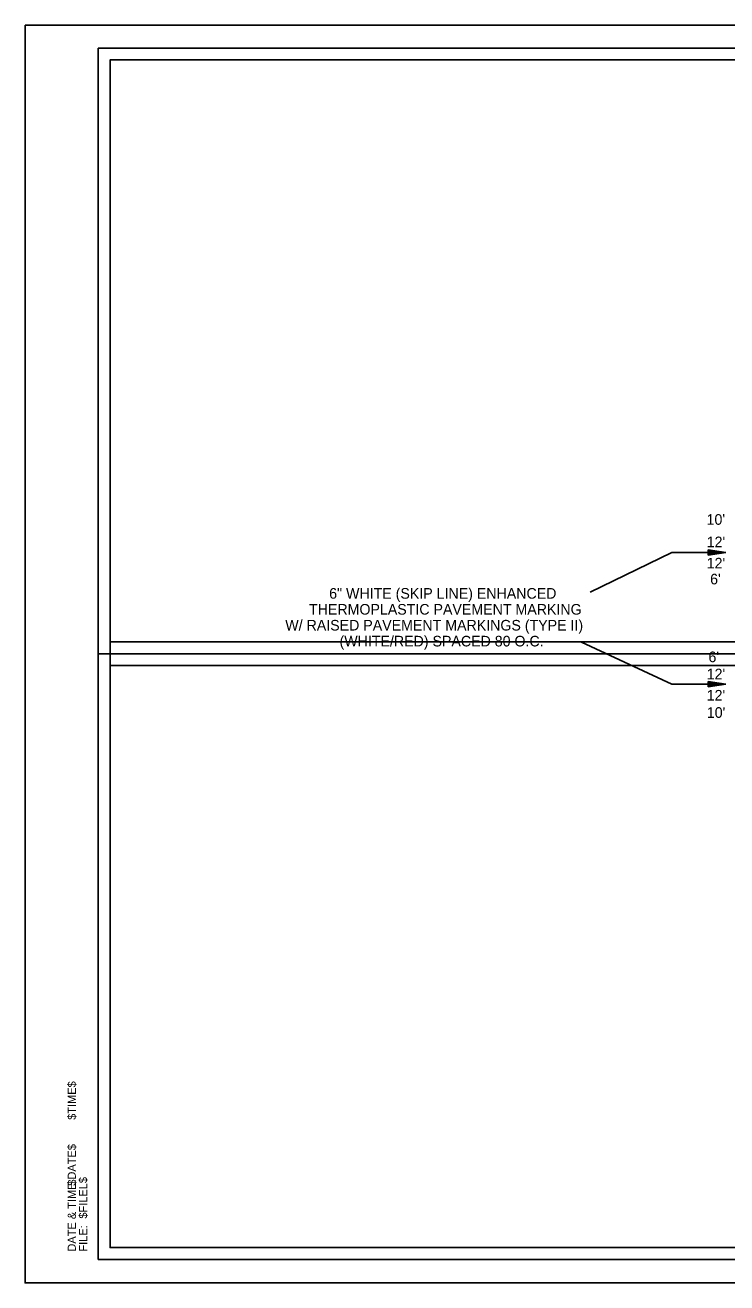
# Model space of a CAD drawing. Extents: x 1369905 to 1370238, y 380119 to 380332.
# Drawn here: x 1369904.7 to 1370023.8, y 380119.1 to 380332.4 of the extents above; entities that cross this region are included whole.
import ezdxf

# ---------------------------------------------------------------- set-up
doc = ezdxf.new("R2010")
doc.units = 0
for name, color, linetype in [('Default', 7, 'Continuous'), ('R_Border', 7, 'Continuous'), ('R_Border Notes', 7, 'Continuous'), ('R_Border Plan-Plan', 7, 'Continuous'), ('R_No Plot', 7, 'Continuous'), ('R_Proposed Road', 7, 'Continuous')]:
    doc.layers.add(name, color=color, linetype=linetype)

msp = doc.modelspace()

# ---------------------------------------------------------------- linework, layer by layer
at = {"layer": 'Default'}
for p, q in [((1370020.65, 380243.42), (1370023.65, 380242.97)), ((1370020.65, 380243.42), (1370020.65, 380242.52)), ((1370020.65, 380243.42), (1370023.65, 380242.97)), ((1370020.65, 380243.42), (1370020.65, 380242.52)), ((1370020.65, 380243.42), (1370023.65, 380242.97)), ((1370020.65, 380243.42), (1370020.65, 380242.52)), ((1370020.65, 380243.33), (1370023.15, 380242.97)), ((1370020.65, 380243.33), (1370023.15, 380242.97)), ((1370020.65, 380243.33), (1370023.15, 380242.97)), ((1370020.65, 380243.27), (1370022.63, 380242.97)), ((1370020.65, 380243.27), (1370022.63, 380242.97)), ((1370020.65, 380243.27), (1370022.63, 380242.97)), ((1370020.65, 380243.18), (1370022.13, 380242.97)), ((1370020.65, 380243.18), (1370022.13, 380242.97)), ((1370020.65, 380243.18), (1370022.13, 380242.97)), ((1370020.65, 380243.12), (1370021.62, 380242.97)), ((1370020.65, 380243.12), (1370021.62, 380242.97)), ((1370020.65, 380243.12), (1370021.62, 380242.97)), ((1370020.65, 380243.03), (1370021.12, 380242.97)), ((1370020.65, 380243.03), (1370021.12, 380242.97)), ((1370020.65, 380243.03), (1370021.12, 380242.97)), ((1370020.65, 380242.52), (1370023.65, 380242.97)), ((1370020.65, 380242.82), (1370021.62, 380242.97)), ((1370020.65, 380242.67), (1370022.63, 380242.97)), ((1370020.65, 380242.6), (1370023.15, 380242.97)), ((1370020.65, 380242.75), (1370022.13, 380242.97)), ((1370020.65, 380242.9), (1370021.12, 380242.97)), ((1370020.65, 380242.52), (1370023.65, 380242.97)), ((1370020.65, 380242.82), (1370021.62, 380242.97)), ((1370020.65, 380242.67), (1370022.63, 380242.97)), ((1370020.65, 380242.6), (1370023.15, 380242.97)), ((1370020.65, 380242.75), (1370022.13, 380242.97)), ((1370020.65, 380242.9), (1370021.12, 380242.97)), ((1370020.65, 380242.52), (1370023.65, 380242.97)), ((1370020.65, 380242.82), (1370021.62, 380242.97)), ((1370020.65, 380242.67), (1370022.63, 380242.97)), ((1370020.65, 380242.6), (1370023.15, 380242.97)), ((1370020.65, 380242.75), (1370022.13, 380242.97)), ((1370020.65, 380242.9), (1370021.12, 380242.97)), ((1370020.65, 380221.06), (1370023.65, 380220.61)), ((1370020.65, 380220.16), (1370020.65, 380221.06)), ((1370020.65, 380221.06), (1370023.65, 380220.61)), ((1370020.65, 380220.16), (1370020.65, 380221.06)), ((1370020.65, 380221.06), (1370023.65, 380220.61)), ((1370020.65, 380220.16), (1370020.65, 380221.06)), ((1370020.65, 380220.98), (1370023.15, 380220.61)), ((1370020.65, 380220.98), (1370023.15, 380220.61)), ((1370020.65, 380220.98), (1370023.15, 380220.61)), ((1370020.65, 380220.91), (1370022.63, 380220.61)), ((1370020.65, 380220.91), (1370022.63, 380220.61)), ((1370020.65, 380220.91), (1370022.63, 380220.61)), ((1370020.65, 380220.83), (1370022.13, 380220.61)), ((1370020.65, 380220.83), (1370022.13, 380220.61)), ((1370020.65, 380220.83), (1370022.13, 380220.61)), ((1370020.65, 380220.76), (1370021.62, 380220.61)), ((1370020.65, 380220.76), (1370021.62, 380220.61)), ((1370020.65, 380220.76), (1370021.62, 380220.61)), ((1370020.65, 380220.68), (1370021.12, 380220.61)), ((1370020.65, 380220.68), (1370021.12, 380220.61)), ((1370020.65, 380220.68), (1370021.12, 380220.61)), ((1370020.65, 380220.16), (1370023.65, 380220.61)), ((1370020.65, 380220.46), (1370021.62, 380220.61)), ((1370020.65, 380220.31), (1370022.63, 380220.61)), ((1370020.65, 380220.24), (1370023.15, 380220.61)), ((1370020.65, 380220.39), (1370022.13, 380220.61)), ((1370020.65, 380220.54), (1370021.12, 380220.61)), ((1370020.65, 380220.16), (1370023.65, 380220.61)), ((1370020.65, 380220.46), (1370021.62, 380220.61)), ((1370020.65, 380220.31), (1370022.63, 380220.61)), ((1370020.65, 380220.24), (1370023.15, 380220.61)), ((1370020.65, 380220.39), (1370022.13, 380220.61)), ((1370020.65, 380220.54), (1370021.12, 380220.61)), ((1370020.65, 380220.16), (1370023.65, 380220.61)), ((1370020.65, 380220.46), (1370021.62, 380220.61)), ((1370020.65, 380220.31), (1370022.63, 380220.61)), ((1370020.65, 380220.24), (1370023.15, 380220.61)), ((1370020.65, 380220.39), (1370022.13, 380220.61)), ((1370020.65, 380220.54), (1370021.12, 380220.61))]:
    msp.add_line(p, q, dxfattribs=at)
at = {"layer": 'R_Border'}
for p, q in [((1369917.1, 380328.52), (1370233.28, 380328.52)), ((1369917.1, 380123.06), (1369917.1, 380328.52)), ((1369917.1, 380123.06), (1369917.1, 380123.06)), ((1370233.28, 380123.06), (1369917.1, 380123.06))]:
    msp.add_line(p, q, dxfattribs=at)
at = {"layer": 'R_Border Plan-Plan'}
msp.add_line((1369917.1, 380225.79), (1370233.28, 380225.79), dxfattribs=at)
at = {"layer": 'R_No Plot'}
for points in [[(1369904.69, 380332.42), (1370238.03, 380332.42), (1370238.03, 380119.08), (1369904.69, 380119.08)], [(1370231.28, 380227.79), (1369919.1, 380227.79), (1369919.1, 380326.52), (1370168.64, 380326.52), (1370168.64, 380316.64), (1370186.18, 380316.64), (1370210.28, 380316.64), (1370210.28, 380294.31), (1370231.28, 380294.31)], [(1369919.1, 380326.52), (1370168.64, 380326.52), (1370168.64, 380316.64), (1370186.18, 380316.64), (1370210.28, 380316.64), (1370210.28, 380294.31), (1370231.28, 380294.31), (1370231.28, 380125.06), (1369919.1, 380125.06)], [(1369919.1, 380223.79), (1370231.28, 380223.79), (1370231.28, 380125.06), (1369919.1, 380125.06)]]:
    msp.add_lwpolyline(points, close=True, dxfattribs=at)
at = {"layer": 'R_Proposed Road'}
for p, q in [((1370014.44, 380242.97), (1370023.65, 380242.97)), ((1370014.44, 380242.97), (1370023.65, 380242.97)), ((1370014.44, 380220.61), (1370023.65, 380220.61)), ((1370014.44, 380220.61), (1370023.65, 380220.61))]:
    msp.add_line(p, q, dxfattribs=at)
for points in [[(1370000.62, 380236.26), (1370014.44, 380242.97), (1370023.65, 380242.97)], [(1369999.13, 380227.74), (1370014.44, 380220.61), (1370023.65, 380220.61)]]:
    msp.add_lwpolyline(points, dxfattribs=at)

# ---------------------------------------------------------------- texts
at = {"layer": 'Default'}
for s, p in [("10'", (1370020.36, 380247.67)), ("12'", (1370020.38, 380243.86)), ("12'", (1370020.38, 380240.26)), ("6'", (1370020.96, 380237.56)), ("6'", (1370020.68, 380224.36)), ("12'", (1370020.38, 380221.45)), ("12'", (1370020.38, 380217.85)), ("10'", (1370020.4, 380214.92))]:
    msp.add_text(s, height=1.8, rotation=360, dxfattribs=at).set_placement(p)
for s, p in [('6" WHITE (SKIP LINE) ENHANCED ', (1369956.3, 380235.13)), ('THERMOPLASTIC PAVEMENT MARKING', (1369952.88, 380232.43)), ('W/ RAISED PAVEMENT MARKINGS (TYPE II)', (1369948.85, 380229.73)), ('(WHITE/RED) SPACED 80 O.C.', (1369958.06, 380227.03))]:
    msp.add_text(s, height=1.8, dxfattribs=at).set_placement(p)
at = {"layer": 'R_Border Notes'}
for s, height, p in [('$TIME$', 1.397, (1369913.3, 380146.73)), ('$DATE$', 1.397, (1369913.3, 380135.56)), ('DATE & TIME:', 1.3968, (1369913.3, 380124.38)), ('$FILEL$', 1.397, (1369915.22, 380129.97)), ('FILE: ', 1.397, (1369915.22, 380124.38))]:
    msp.add_text(s, height=height, rotation=90, dxfattribs=at).set_placement(p)

doc.saveas('drawing.dxf')
